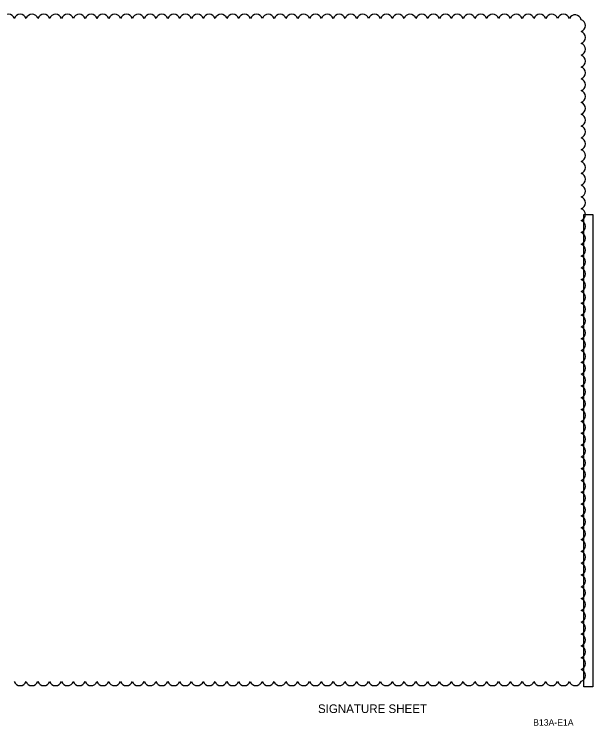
# Model space of a CAD drawing. Extents: x -811.3 to -795.2, y -2199.5 to -2188.9.
# Drawn here: x -803.6 to -795.22, y -2199.24 to -2188.94 of the extents above; entities that cross this region are included whole.
import ezdxf

# ---------------------------------------------------------------- set-up
doc = ezdxf.new("R2010")
doc.units = 0
for name, color, linetype in [('AdhocPoint_dp', 7, 'Continuous'), ('ScratchEle_dp', 7, 'Continuous'), ('SheetBorder_dp', 7, 'Continuous'), ('TextMisc', 7, 'Continuous')]:
    doc.layers.add(name, color=color, linetype=linetype)

msp = doc.modelspace()

# ---------------------------------------------------------------- linework, layer by layer
at = {"layer": 'ScratchEle_dp'}
for centre, radius, start, end in [((-803.684, -2189.028), 0.0897, 17.5, 162.5), ((-803.513, -2189.028), 0.0897, 17.5, 162.5), ((-803.342, -2189.028), 0.0897, 17.5, 162.5), ((-803.171, -2189.028), 0.0897, 17.5, 162.5), ((-803, -2189.028), 0.0897, 17.5, 162.5), ((-802.829, -2189.028), 0.0897, 17.5, 162.5), ((-802.657, -2189.028), 0.0897, 17.5, 162.5), ((-802.486, -2189.028), 0.0897, 17.5, 162.5), ((-802.315, -2189.028), 0.0897, 17.5, 162.5), ((-802.144, -2189.028), 0.0897, 17.5, 162.5), ((-801.973, -2189.028), 0.0897, 17.5, 162.5), ((-801.802, -2189.028), 0.0897, 17.5, 162.5), ((-801.631, -2189.028), 0.0897, 17.5, 162.5), ((-801.46, -2189.028), 0.0897, 17.5, 162.5), ((-801.288, -2189.028), 0.0897, 17.5, 162.5), ((-801.117, -2189.028), 0.0897, 17.5, 162.5), ((-800.946, -2189.028), 0.0897, 17.5, 162.5), ((-800.775, -2189.028), 0.0897, 17.5, 162.5), ((-800.604, -2189.028), 0.0897, 17.5, 162.5), ((-800.433, -2189.028), 0.0897, 17.5, 162.5), ((-800.262, -2189.028), 0.0897, 17.5, 162.5), ((-800.091, -2189.028), 0.0897, 17.5, 162.5), ((-799.919, -2189.028), 0.0897, 17.5, 162.5), ((-799.748, -2189.028), 0.0897, 17.5, 162.5), ((-799.577, -2189.028), 0.0897, 17.5, 162.5), ((-799.406, -2189.028), 0.0897, 17.5, 162.5), ((-799.235, -2189.028), 0.0897, 17.5, 162.5), ((-799.064, -2189.028), 0.0897, 17.5, 162.5), ((-798.893, -2189.028), 0.0897, 17.5, 162.5), ((-798.722, -2189.028), 0.0897, 17.5, 162.5), ((-798.551, -2189.028), 0.0897, 17.5, 162.5), ((-798.379, -2189.028), 0.0897, 17.5, 162.5), ((-798.208, -2189.028), 0.0897, 17.5, 162.5), ((-798.037, -2189.028), 0.0897, 17.5, 162.5), ((-797.866, -2189.028), 0.0897, 17.5, 162.5), ((-797.695, -2189.028), 0.0897, 17.5, 162.5), ((-797.524, -2189.028), 0.0897, 17.5, 162.5), ((-797.353, -2189.028), 0.0897, 17.5, 162.5), ((-797.182, -2189.028), 0.0897, 17.5, 162.5), ((-797.01, -2189.028), 0.0897, 17.5, 162.5), ((-796.839, -2189.028), 0.0897, 17.5, 162.5), ((-796.668, -2189.028), 0.0897, 17.5, 162.5), ((-796.497, -2189.028), 0.0897, 17.5, 162.5), ((-796.326, -2189.028), 0.0897, 17.5, 162.5), ((-796.155, -2189.028), 0.0897, 17.5, 162.5), ((-795.984, -2189.028), 0.0897, 17.5, 162.5), ((-795.813, -2189.028), 0.0897, 17.5, 162.5), ((-795.641, -2189.028), 0.0897, 17.5, 162.5), ((-795.474, -2189.036), 0.0896, 11.7454, 156.7454), ((-795.413, -2189.103), 0.0897, 287.5, 72.5), ((-795.413, -2189.274), 0.0897, 287.5, 72.5), ((-795.413, -2189.446), 0.0897, 287.5, 72.5), ((-795.413, -2189.617), 0.0897, 287.5, 72.5), ((-795.413, -2189.788), 0.0897, 287.5, 72.5), ((-795.413, -2189.959), 0.0897, 287.5, 72.5), ((-795.413, -2190.13), 0.0897, 287.5, 72.5), ((-795.413, -2190.301), 0.0897, 287.5, 72.5), ((-795.413, -2190.472), 0.0897, 287.5, 72.5), ((-795.413, -2190.643), 0.0897, 287.5, 72.5), ((-795.413, -2190.815), 0.0897, 287.5, 72.5), ((-795.413, -2190.986), 0.0897, 287.5, 72.5), ((-795.413, -2191.157), 0.0897, 287.5, 72.5), ((-795.413, -2191.328), 0.0897, 287.5, 72.5), ((-795.413, -2191.499), 0.0897, 287.5, 72.5), ((-795.413, -2191.67), 0.0897, 287.5, 72.5), ((-795.413, -2191.841), 0.0897, 287.5, 72.5), ((-795.413, -2192.012), 0.0897, 287.5, 72.5), ((-795.413, -2192.184), 0.0897, 287.5, 72.5), ((-795.413, -2192.355), 0.0897, 287.5, 72.5), ((-795.413, -2192.526), 0.0897, 287.5, 72.5), ((-795.413, -2192.697), 0.0897, 287.5, 72.5), ((-795.413, -2192.868), 0.0897, 287.5, 72.5), ((-795.413, -2193.039), 0.0897, 287.5, 72.5), ((-795.413, -2193.21), 0.0897, 287.5, 72.5), ((-795.413, -2193.381), 0.0897, 287.5, 72.5), ((-795.413, -2193.553), 0.0897, 287.5, 72.5), ((-795.413, -2193.724), 0.0897, 287.5, 72.5), ((-795.413, -2193.895), 0.0897, 287.5, 72.5), ((-795.413, -2194.066), 0.0897, 287.5, 72.5), ((-795.413, -2194.237), 0.0897, 287.5, 72.5), ((-795.413, -2194.408), 0.0897, 287.5, 72.5), ((-795.413, -2194.579), 0.0897, 287.5, 72.5), ((-795.413, -2194.75), 0.0897, 287.5, 72.5), ((-795.413, -2194.922), 0.0897, 287.5, 72.5), ((-795.413, -2195.093), 0.0897, 287.5, 72.5), ((-795.413, -2195.264), 0.0897, 287.5, 72.5), ((-795.413, -2195.435), 0.0897, 287.5, 72.5), ((-795.413, -2195.606), 0.0897, 287.5, 72.5), ((-795.413, -2195.777), 0.0897, 287.5, 72.5), ((-795.413, -2195.948), 0.0897, 287.5, 72.5), ((-795.413, -2196.119), 0.0897, 287.5, 72.5), ((-795.413, -2196.29), 0.0897, 287.5, 72.5), ((-795.413, -2196.462), 0.0897, 287.5, 72.5), ((-795.413, -2196.633), 0.0897, 287.5, 72.5), ((-795.413, -2196.804), 0.0897, 287.5, 72.5), ((-795.413, -2196.975), 0.0897, 287.5, 72.5), ((-795.413, -2197.146), 0.0897, 287.5, 72.5), ((-795.413, -2197.317), 0.0897, 287.5, 72.5), ((-795.413, -2197.488), 0.0897, 287.5, 72.5), ((-795.413, -2197.659), 0.0897, 287.5, 72.5), ((-795.413, -2197.831), 0.0897, 287.5, 72.5), ((-795.413, -2198.002), 0.0897, 287.5, 72.5), ((-795.413, -2198.173), 0.0897, 287.5, 72.5), ((-795.413, -2198.344), 0.0897, 287.5, 72.5), ((-795.413, -2198.515), 0.0897, 287.5, 72.5), ((-803.514, -2198.574), 0.0897, 197.5, 342.5), ((-803.343, -2198.574), 0.0897, 197.5, 342.5), ((-803.172, -2198.574), 0.0897, 197.5, 342.5), ((-803.001, -2198.574), 0.0897, 197.5, 342.5), ((-802.83, -2198.574), 0.0897, 197.5, 342.5), ((-802.658, -2198.574), 0.0897, 197.5, 342.5), ((-802.487, -2198.574), 0.0897, 197.5, 342.5), ((-802.316, -2198.574), 0.0897, 197.5, 342.5), ((-802.145, -2198.574), 0.0897, 197.5, 342.5), ((-801.974, -2198.574), 0.0897, 197.5, 342.5), ((-801.803, -2198.574), 0.0897, 197.5, 342.5), ((-801.632, -2198.574), 0.0897, 197.5, 342.5), ((-801.461, -2198.574), 0.0897, 197.5, 342.5), ((-801.289, -2198.574), 0.0897, 197.5, 342.5), ((-801.118, -2198.574), 0.0897, 197.5, 342.5), ((-800.947, -2198.574), 0.0897, 197.5, 342.5), ((-800.776, -2198.574), 0.0897, 197.5, 342.5), ((-800.605, -2198.574), 0.0897, 197.5, 342.5), ((-800.434, -2198.574), 0.0897, 197.5, 342.5), ((-800.263, -2198.574), 0.0897, 197.5, 342.5), ((-800.092, -2198.574), 0.0897, 197.5, 342.5), ((-799.921, -2198.574), 0.0897, 197.5, 342.5), ((-799.749, -2198.574), 0.0897, 197.5, 342.5), ((-799.578, -2198.574), 0.0897, 197.5, 342.5), ((-799.407, -2198.574), 0.0897, 197.5, 342.5), ((-799.236, -2198.574), 0.0897, 197.5, 342.5), ((-799.065, -2198.574), 0.0897, 197.5, 342.5), ((-798.894, -2198.574), 0.0897, 197.5, 342.5), ((-798.723, -2198.574), 0.0897, 197.5, 342.5), ((-798.552, -2198.574), 0.0897, 197.5, 342.5), ((-798.38, -2198.574), 0.0897, 197.5, 342.5), ((-798.209, -2198.574), 0.0897, 197.5, 342.5), ((-798.038, -2198.574), 0.0897, 197.5, 342.5), ((-797.867, -2198.574), 0.0897, 197.5, 342.5), ((-797.696, -2198.574), 0.0897, 197.5, 342.5), ((-797.525, -2198.574), 0.0897, 197.5, 342.5), ((-797.354, -2198.574), 0.0897, 197.5, 342.5), ((-797.183, -2198.574), 0.0897, 197.5, 342.5), ((-797.011, -2198.574), 0.0897, 197.5, 342.5), ((-796.84, -2198.574), 0.0897, 197.5, 342.5), ((-796.669, -2198.574), 0.0897, 197.5, 342.5), ((-796.498, -2198.574), 0.0897, 197.5, 342.5), ((-796.327, -2198.574), 0.0897, 197.5, 342.5), ((-796.156, -2198.574), 0.0897, 197.5, 342.5), ((-795.985, -2198.574), 0.0897, 197.5, 342.5), ((-795.814, -2198.574), 0.0897, 197.5, 342.5), ((-795.642, -2198.574), 0.0897, 197.5, 342.5), ((-795.471, -2198.574), 0.0897, 197.5, 342.5)]:
    msp.add_arc(centre, radius, start, end, dxfattribs=at)
at = {"layer": 'TextMisc'}
msp.add_lwpolyline([(-795.346, -2191.838), (-795.218, -2191.838), (-795.218, -2198.68), (-795.346, -2198.68)], close=True, dxfattribs=at)

# ---------------------------------------------------------------- texts
at = {"layer": 'AdhocPoint_dp'}
msp.add_text('B13A-E1A', height=0.0936, dxfattribs=at).set_placement((-796.081, -2199.243))
at = {"layer": 'SheetBorder_dp'}
msp.add_text('       SIGNATURE SHEET         ', height=0.125, dxfattribs=at).set_placement((-799.524, -2199.06))

doc.saveas('drawing.dxf')
